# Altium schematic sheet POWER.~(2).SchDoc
size 431 x 279 mm; Date: Not shown in title block; ApprovedBy: Not shown in title block; CheckedBy: Not shown in title block; Author: Not shown in title block; CompanyName: Not shown in title block; DrawnBy: G. Fiolic; Engineer: Not shown in title block; Organization: Not shown in title block; Address1: Not shown in title block; Address2: Not shown in title block; Address3: Not shown in title block; Address4: Not shown in title block; DocumentNumber: 3; Revision: Use project parameter SCH_Rev; SheetNumber: 3; SheetTotal: 6; PageSetup: Record=PageOptions|CenterHorizontal=True|CenterVertical=True|PrintScale=1.00|XCorrection=1.00|YCorrection=1.00|PrintKind=0|BorderSize=5000000|LeftOffset=0|BottomOffset=0|Orientation=2|PaperLength=1000|PaperWidth=1000|Scale=100|PaperSource=15|PrintQuality=600|MediaType=1|DitherType=10|PaperKind=Letter|PrintScaleMode=1
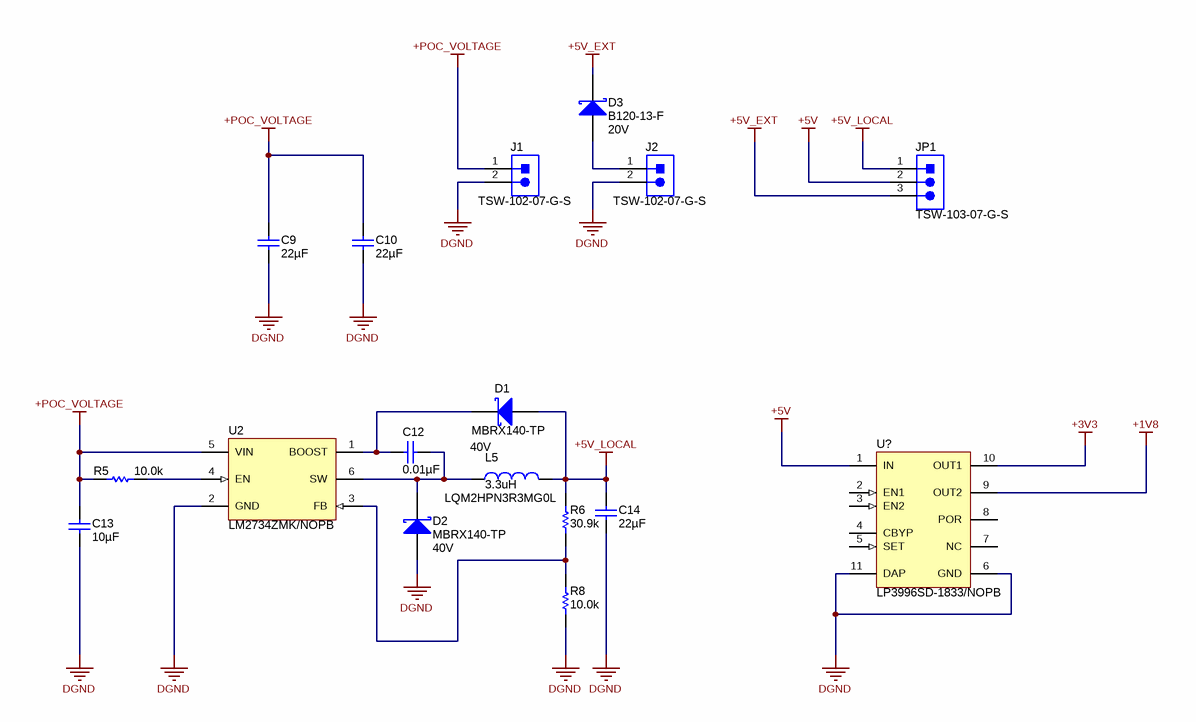
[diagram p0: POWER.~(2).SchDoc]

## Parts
C9  ValueDisplayed: 22µF  [0805]  (hidden comment: C2012X5R1C226K125AC)
C10  ValueDisplayed: 22µF  [0805]  (hidden comment: C2012X5R1C226K125AC)
C12  ValueDisplayed: 0.01µF  [0402L]  (hidden comment: GRM155R71H103KA88D)
C13  ValueDisplayed: 10µF  [1206L]  (hidden comment: GRM31CR71E106KA12L)
C14  ValueDisplayed: 22µF  [0805]  (hidden comment: C2012X5R1C226K125AC)
D1  MBRX140-TP  value 40V  [SOD-123]
D2  MBRX140-TP  value 40V  [SOD-123]
D3  B120-13-F  value 20V  [SMA]
J1  TSW-102-07-G-S  [TSW-102-07-G-S]
J2  TSW-102-07-G-S  [TSW-102-07-G-S]
JP1  TSW-103-07-G-S  [TSW-103-07-G-S]
L5  LQM2HPN3R3MG0L  value 3.3uH  [IND_1008]
R5  value 10.0k  [0402L]  (hidden comment: CRCW040210K0FKED)
R6  value 30.9k  [0402L]  (hidden comment: CRCW040230K9FKED)
R8  value 10.0k  [0402L]  (hidden comment: CRCW040210K0FKED)
U2  LM2734ZMK/NOPB  [MK06A_N]
U?  LP3996SD-1833/NOPB  [SDA10A]

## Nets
+1V8: U?.9(OUT2)
+3V3: U?.10(OUT1)
+5V: JP1.2 U?.1(IN)
+5V_EXT: D3.1(K) JP1.3
+5V_LOCAL: C14.1 D1.2(A) JP1.1 L5.2 R6.1
+POC_VOLTAGE: C9.1 C10.1 C13.1 J1.1 R5.1 U2.5(VIN)
DGND: C9.2 C10.2 C13.2 C14.2 D2.2(A) J1.2 J2.2 R8.2 U2.2(GND) U?.6(GND) U?.11(DAP)
NetC12_1: C12.1 D1.1(K) U2.1(BOOST)
NetC12_2: C12.2 D2.1(K) L5.1 U2.6(SW)
NetD3_2: D3.2(A) J2.1
NetR5_2: R5.2 U2.4(EN)
NetR6_2: R6.2 R8.1 U2.3(FB)

Not connected (* = marked no-connect by the designer): U? 2(EN1) 3(EN2) 4(CBYP) 5(SET) 7(NC) 8(POR)

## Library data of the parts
C9 C10 C14 = C2012X5R1C226K125AC: CAP, CERM, 22uF, 16V, +/-10%, X5R, 0805; Manufacturer: TDK; Polarized: N; CompType: Capacitor; U/M: EA; Cap_F: 0.000022; Tolerance_%: 10; Value1: Unknown; VDC_V: 16; TaMin_C: -55; TaMax_C: 85
C12 = GRM155R71H103KA88D: CAP, CERM, 0.01uF, 50V, +/-10%, X7R, 0402; Manufacturer: MuRata; Polarized: N; CompType: Capacitor; U/M: EA; Cap_F: 0.00000001; Tolerance_%: 10; Value1: Unknown; VDC_V: 50; TaMin_C: -55; TaMax_C: 125; Cap_Case: 0402
C13 = GRM31CR71E106KA12L: CAP, CERM, 10uF, 25V, +/-10%, X7R, 1206; Manufacturer: MuRata; Polarized: N; CompType: Capacitor; U/M: EA; Cap_F: 0.00001; Tolerance_%: 10; Value1: Unknown; VDC_V: 25; TaMin_C: -55; TaMax_C: 125; Cap_Case: 2220
D1 D2 = Diode_Schottky: Diode, Schottky, 40V, 1A, SOD-123; Manufacturer: Micro Commercial Co; U/M: EA
D3 = B120-13-F: Diode, Schottky, 20V, 1A, SMA; Manufacturer: Diodes Inc.; U/M: EA; Vf_V: 0.5; Value2: 0.5V; Io_A: 1; Vr_V: 20; TJmax_C: 150
J1 J2 = TSW-102-07-G-S: Header, TH, 100mil, 2x1, Gold plated, 230 mil above insulator; Manufacturer: Samtec; SymbolCreator: a0412235; U/M: EA
JP1 = TSW-103-07-G-S: Header, TH, 100mil, 3x1, Gold plated, 230 mil above insulator; Manufacturer: Samtec; SymbolCreator: a0799628; U/M: EA
L5 = Inductor: Inductor, Shielded 3.3uH, 1200mA, 100 mohm, Surface Mount; Manufacturer: Murata Electronics North America; U/M: EA
R5 R8 = CRCW040210K0FKED: RES, 10.0k ohm, 1%, 0.063W, 0402; Manufacturer: Vishay-Dale; CompType: Resistor; Res_ohm: 10000; Value_Code: 10k0; Tolerance_%: 1; Power_W: 0.063; VDC_V: 50; TempCo: 100 ppm/C; EIA_Code: E96; U/M: EA
R6 = CRCW040230K9FKED: RES, 30.9k ohm, 1%, 0.063W, 0402; Manufacturer: Vishay-Dale; CompType: Resistor; Res_ohm: 30900; Value_Code: 30k9; Tolerance_%: 1; Power_W: 0.063; VDC_V: 50; TempCo: 100 ppm/C; EIA_Code: E96; U/M: EA
U2 = LM2734ZMK/NOPB: 1A Load Step-Down DC-DC Regulator, 6-pin Tiny SOT23, Pb-Free; Manufacturer: National Semiconductor; PackageTopMarking: SFTB*XTT; PowerWise: N; CompType: Switcher
U? = LP3996SD-1833/NOPB: Dual Linear Regulator with 300mA and 150mA Outputs and Power-On-Reset, 10-pin LLP, Pb-Free; Manufacturer: National Semiconductor; PackageTopMarking: ZXYTT*L228B; PowerWise: N; CompType: LDO IC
